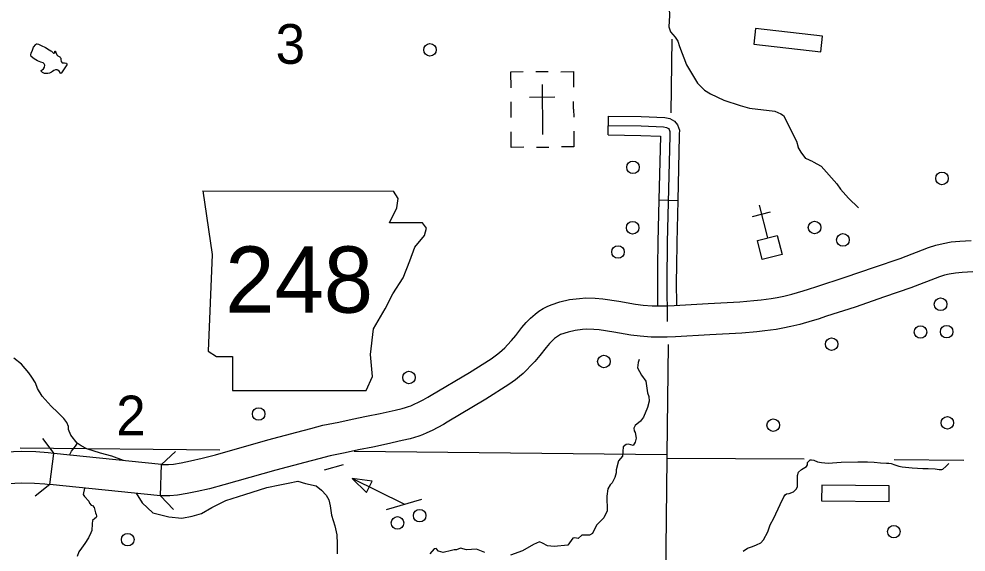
# Model space of a CAD drawing. Extents: x 1382482 to 1385815, y 1168351 to 1170484.
# Drawn here: x 1383865.9 to 1384167.8, y 1168828.2 to 1168998.2 of the extents above; entities that cross this region are included whole.
import ezdxf

# ---------------------------------------------------------------- set-up
doc = ezdxf.new("R2010")
doc.units = 0
for name, color, linetype in [('10', 7, 'Continuous'), ('21', 7, 'Continuous'), ('35', 7, 'Continuous'), ('37', 7, 'Continuous'), ('4', 7, 'Continuous'), ('45', 7, 'Continuous'), ('5', 7, 'Continuous'), ('57', 7, 'Continuous'), ('Default', 7, 'Continuous')]:
    doc.layers.add(name, color=color, linetype=linetype)

msp = doc.modelspace()

# ---------------------------------------------------------------- linework, layer by layer
at = {"layer": '10'}
for points in [[(1384035.51, 1168907.02), (1384038.28, 1168907.91), (1384041.38, 1168908.64), (1384044.58, 1168909.06), (1384046.58, 1168909.19), (1384049.61, 1168909.13), (1384052.01, 1168908.95), (1384057.11, 1168908.12), (1384062.4, 1168907.24), (1384064.88, 1168906.91), (1384067.79, 1168906.72), (1384072.42, 1168906.64), (1384074.72, 1168906.74), (1384085.56, 1168907.42), (1384095.67, 1168907.95), (1384100.13, 1168908.34), (1384102.5, 1168908.59), (1384105.71, 1168909.02), (1384107.58, 1168909.36), (1384109.77, 1168909.8), (1384112.26, 1168910.43), (1384115.91, 1168911.45), (1384117.59, 1168911.97), (1384120.25, 1168912.86), (1384129.31, 1168915.77), (1384138.6, 1168918.97), (1384146.83, 1168921.78), (1384155.88, 1168925.25), (1384158.16, 1168926.07), (1384160.51, 1168926.58), (1384163.12, 1168927.03), (1384165.85, 1168927.3), (1384169.46, 1168927.46)], [(1384169.94, 1168917.47), (1384166.56, 1168917.32), (1384164.47, 1168917.12), (1384162.43, 1168916.76), (1384160.9, 1168916.43), (1384159.35, 1168915.88), (1384150.24, 1168912.37), (1384141.84, 1168909.51), (1384132.47, 1168906.28), (1384123.37, 1168903.36), (1384120.64, 1168902.44), (1384118.71, 1168901.85), (1384114.85, 1168900.77), (1384111.99, 1168900.04), (1384109.46, 1168899.54), (1384107.28, 1168899.14), (1384103.7, 1168898.66), (1384101.08, 1168898.38), (1384096.36, 1168897.98), (1384086.13, 1168897.44), (1384075.24, 1168896.75), (1384072.55, 1168896.64), (1384067.38, 1168896.72), (1384063.88, 1168896.95), (1384060.91, 1168897.35), (1384055.49, 1168898.25), (1384050.83, 1168899.01), (1384049.13, 1168899.14), (1384046.81, 1168899.18), (1384045.56, 1168899.1), (1384043.19, 1168898.79), (1384040.94, 1168898.26), (1384038.56, 1168897.5)], [(1383911.35, 1168856.09), (1383911.55, 1168856.09), (1383913.5, 1168856.09), (1383915.15, 1168856.23), (1383917.61, 1168856.65), (1383920.61, 1168857.27), (1383924.24, 1168858.07), (1383928.53, 1168859.19), (1383945.17, 1168863.94), (1383954.43, 1168866.37), (1383958.89, 1168867.58), (1383962.79, 1168868.57), (1383967.85, 1168869.62), (1383972.1, 1168870.53), (1383976.69, 1168871.44), (1383980.99, 1168872.34), (1383985.83, 1168873.42), (1383988.06, 1168873.95), (1383989.08, 1168874.24), (1383990.03, 1168874.54), (1383990.78, 1168874.83), (1383991.83, 1168875.28), (1383993.25, 1168875.93), (1383994.73, 1168876.7), (1383996.21, 1168877.5), (1383997.25, 1168878.14), (1384009.53, 1168885.39), (1384016.42, 1168889.81), (1384018.11, 1168891.05), (1384019.12, 1168891.83), (1384019.94, 1168892.55), (1384020.75, 1168893.31), (1384021.67, 1168894.28), (1384022.85, 1168895.58), (1384024.24, 1168897.19), (1384026.22, 1168899.73), (1384027.59, 1168901.32), (1384028.94, 1168902.78), (1384030.4, 1168904.06), (1384031.64, 1168904.96), (1384033.02, 1168905.83), (1384034.22, 1168906.44), (1384035.51, 1168907.02)], [(1384038.56, 1168897.5), (1384037.25, 1168896.67), (1384036.64, 1168896.23), (1384035.93, 1168895.61), (1384035.04, 1168894.65), (1384033.95, 1168893.39), (1384031.97, 1168890.84), (1384030.34, 1168888.95), (1384029.01, 1168887.49), (1384027.81, 1168886.22), (1384026.64, 1168885.12), (1384025.48, 1168884.11), (1384024.15, 1168883.08), (1384022.09, 1168881.56), (1384014.77, 1168876.87), (1384002.41, 1168869.58), (1384001.21, 1168868.83), (1383999.41, 1168867.86), (1383997.65, 1168866.95), (1383995.89, 1168866.14), (1383994.52, 1168865.55), (1383993.33, 1168865.1), (1383991.99, 1168864.67), (1383990.59, 1168864.27), (1383988.07, 1168863.68), (1383983.1, 1168862.56), (1383978.68, 1168861.64), (1383974.12, 1168860.74), (1383969.92, 1168859.84), (1383965.04, 1168858.82), (1383961.43, 1168857.91), (1383957.01, 1168856.7), (1383947.8, 1168854.29), (1383931.17, 1168849.55), (1383926.57, 1168848.34), (1383922.7, 1168847.49), (1383919.48, 1168846.82), (1383916.42, 1168846.3), (1383913.92, 1168846.09), (1383911.39, 1168846.09), (1383911.03, 1168846.1), (1383911.35, 1168856.09)], [(1383875.74, 1168849.68), (1383877.01, 1168859.6), (1383875.13, 1168859.84), (1383871.26, 1168860.1), (1383866.76, 1168860.19), (1383864.1, 1168860.1), (1383860.56, 1168859.89), (1383855.45, 1168859.33), (1383849.15, 1168858.42), (1383842.26, 1168857.43), (1383831.66, 1168855.79), (1383823.49, 1168854.48), (1383815.39, 1168853.18)], [(1383911.35, 1168856.09), (1383877.01, 1168859.6)], [(1383815.39, 1168853.18), (1383816.97, 1168843.31), (1383825.07, 1168844.61), (1383833.22, 1168845.91), (1383843.73, 1168847.54), (1383850.57, 1168848.52), (1383856.71, 1168849.41), (1383861.41, 1168849.92), (1383864.57, 1168850.11), (1383866.83, 1168850.19), (1383870.83, 1168850.11), (1383874.16, 1168849.88), (1383875.74, 1168849.68)], [(1383911.03, 1168846.1), (1383875.74, 1168849.68)]]:
    msp.add_lwpolyline(points, dxfattribs=at)
at = {"layer": '21'}
for p, q in [((1383924.46, 1168943.3), (1383927.5, 1168923)), ((1383986.72, 1168940.93), (1383985.31, 1168943.27)), ((1383986.38, 1168937.89), (1383986.72, 1168940.93)), ((1383984.01, 1168933.15), (1383986.38, 1168937.89)), ((1383994.5, 1168933.15), (1383984.01, 1168933.15)), ((1383995.85, 1168931.46), (1383994.5, 1168933.15)), ((1383995.18, 1168929.09), (1383995.85, 1168931.46)), ((1383992.13, 1168925.37), (1383995.18, 1168929.09)), ((1383990.44, 1168920.97), (1383992.13, 1168925.37)), ((1383927.5, 1168923), (1383926.15, 1168892.21)), ((1383988.41, 1168915.56), (1383990.44, 1168920.97)), ((1383985.02, 1168910.48), (1383988.41, 1168915.56)), ((1383982.66, 1168905.74), (1383985.02, 1168910.48)), ((1383978.93, 1168899.31), (1383982.66, 1168905.74)), ((1383977.92, 1168891.19), (1383978.93, 1168899.31)), ((1383926.15, 1168892.21), (1383928.86, 1168890.52)), ((1383928.86, 1168890.52), (1383933.93, 1168890.52)), ((1383933.93, 1168890.52), (1383933.93, 1168879.69)), ((1383978.6, 1168884.09), (1383977.92, 1168891.19)), ((1383976.57, 1168879.69), (1383978.6, 1168884.09)), ((1383933.93, 1168879.69), (1383976.57, 1168879.69))]:
    msp.add_line(p, q, dxfattribs=at)
msp.add_lwpolyline([(1383924.46, 1168943.3), (1383985.31, 1168943.27)], dxfattribs=at)
at = {"layer": '35'}
for points in [[(1384073.22, 1169001.47), (1384073.28, 1168999.3), (1384073.03, 1168995.62), (1384073.6, 1168994.06), (1384075.1, 1168992.35), (1384075.95, 1168991.03), (1384076.48, 1168989.32), (1384078.72, 1168983.57), (1384082.25, 1168977.71), (1384084.46, 1168975.44), (1384086.31, 1168974.3), (1384090.56, 1168972.29), (1384095.85, 1168970.53), (1384098.78, 1168969.75), (1384106.9, 1168968.74), (1384108.82, 1168967.87), (1384109.58, 1168967.32), (1384113.77, 1168959.14), (1384114.34, 1168957.3)], [(1383874.03, 1168980.8), (1383873.37, 1168981.1), (1383873.13, 1168981.27), (1383872.92, 1168981.53), (1383872.92, 1168981.74), (1383873.25, 1168981.98), (1383873.7, 1168982.27), (1383874.01, 1168982.82), (1383874.09, 1168983.37), (1383873.92, 1168983.82), (1383873.56, 1168984.13), (1383872.84, 1168984.38), (1383871.8, 1168984.83), (1383870.67, 1168985.46), (1383869.75, 1168986.15), (1383869.61, 1168986.71), (1383869.71, 1168987.26), (1383870.14, 1168988.2), (1383870.53, 1168989.18), (1383871.23, 1168989.96), (1383871.49, 1168990.2), (1383871.68, 1168990.23), (1383872.1, 1168990.14), (1383872.9, 1168989.65), (1383874.35, 1168989), (1383875.54, 1168988.36), (1383876.05, 1168987.98), (1383876.24, 1168987.93)], [(1383876.24, 1168987.93), (1383876.73, 1168987.38), (1383876.93, 1168987.24), (1383877.11, 1168987.28), (1383877.26, 1168987.42), (1383877.28, 1168987.69), (1383877.28, 1168987.83), (1383877.32, 1168987.93), (1383877.48, 1168987.83), (1383877.65, 1168987.34), (1383878.01, 1168986.65), (1383878.24, 1168986.4), (1383878.85, 1168986.09), (1383879.04, 1168985.89), (1383879.24, 1168985.62), (1383879.26, 1168985.21), (1383879.38, 1168984.6), (1383879.65, 1168984.21), (1383879.87, 1168984.19), (1383880.43, 1168984.17), (1383880.8, 1168984.09), (1383881.02, 1168984.03), (1383881.1, 1168983.8), (1383881.12, 1168983.56), (1383879.45, 1168980.96), (1383879.24, 1168980.76), (1383879.02, 1168980.82), (1383878.98, 1168981.12), (1383878.73, 1168981.49), (1383878.3, 1168981.84), (1383878.01, 1168981.96), (1383877.5, 1168981.88), (1383876.99, 1168981.68), (1383876.6, 1168981.43), (1383876.21, 1168981.16), (1383875.66, 1168980.86), (1383875.05, 1168980.8), (1383874.27, 1168980.8), (1383874.03, 1168980.8)], [(1384119.12, 1168952.58), (1384116.77, 1168953.68), (1384115.27, 1168955.67), (1384114.34, 1168957.3)], [(1384119.12, 1168952.58), (1384121.64, 1168951.16), (1384126.66, 1168945.56), (1384127.83, 1168943.89), (1384130.32, 1168940.98), (1384133.49, 1168937.97)], [(1383899.24, 1168857.33), (1383895.5, 1168858.73), (1383891.83, 1168859.72), (1383887.56, 1168861.11), (1383885.75, 1168862.05), (1383884.41, 1168862.83), (1383882.43, 1168865.38), (1383881.69, 1168867.23), (1383881.65, 1168868.18), (1383881.09, 1168869.52), (1383880.23, 1168870.73), (1383878.29, 1168872.67), (1383876.17, 1168874.7), (1383873.32, 1168877.9), (1383871.77, 1168880.31), (1383871.17, 1168882.13), (1383870, 1168883.94), (1383869.01, 1168885.28), (1383866.68, 1168888.08), (1383864.27, 1168889.95)], [(1384063.6, 1168889.58), (1384063.28, 1168888.64), (1384063.09, 1168886.88), (1384064.35, 1168884.61), (1384065.72, 1168882.62), (1384066.23, 1168878.98), (1384066.72, 1168877.78), (1384066.81, 1168876.3), (1384066.31, 1168874.21), (1384064.94, 1168871.19), (1384063.99, 1168869.91), (1384062.32, 1168868.53), (1384061.93, 1168867.65), (1384061.98, 1168866.81), (1384062.3, 1168866.25), (1384062.6, 1168864.45), (1384062.37, 1168863.2), (1384061.69, 1168862.16), (1384060.17, 1168862.55), (1384059.49, 1168862.5), (1384058.54, 1168861.69), (1384058.25, 1168858.73), (1384056.98, 1168857.27), (1384056.28, 1168854.38), (1384056.29, 1168853.42), (1384055.82, 1168851.94), (1384054.96, 1168850.25), (1384054.33, 1168849.6), (1384053.66, 1168848.27), (1384053.28, 1168846.03), (1384053.39, 1168841.26), (1384052.29, 1168839.09), (1384049.96, 1168836.71), (1384048.7, 1168834.1), (1384047.82, 1168833.57), (1384045.35, 1168833.51), (1384044.12, 1168832.5), (1384043.12, 1168832.73), (1384042.48, 1168832.6), (1384040.82, 1168830.39), (1384036.54, 1168829.95), (1384034.39, 1168830.1), (1384032.82, 1168831.04), (1384031.86, 1168831.4), (1384029.87, 1168830.54), (1384026.45, 1168828.51)], [(1383881.95, 1168859.09), (1383882.6, 1168860.33), (1383883.85, 1168861.97), (1383884.33, 1168862.57), (1383884.41, 1168862.83)], [(1384096.74, 1168828.39), (1384098.14, 1168829.38), (1384099.69, 1168829.98), (1384101.06, 1168830.46), (1384102.39, 1168831.08), (1384103.28, 1168832.01), (1384104.64, 1168834.63), (1384105.38, 1168836.88), (1384106.56, 1168838.92), (1384108.56, 1168843.31), (1384109.74, 1168845.79), (1384110.18, 1168846.42), (1384110.55, 1168846.68), (1384111.48, 1168846.79), (1384112.8, 1168847.38), (1384113.62, 1168848.19), (1384114.13, 1168848.97), (1384114.1, 1168850.22), (1384114.06, 1168851.55), (1384114.06, 1168852.55), (1384114.39, 1168853.66), (1384115.32, 1168854.47), (1384116.93, 1168855.46), (1384117.23, 1168856.02), (1384117.26, 1168856.68), (1384117.71, 1168857.16), (1384118.08, 1168857.53), (1384118.56, 1168857.53), (1384119.26, 1168857.42), (1384120.51, 1168856.94), (1384121.7, 1168856.76), (1384123.87, 1168856.54), (1384127.97, 1168856.83), (1384133.33, 1168856.9), (1384136.4, 1168856.94), (1384138.54, 1168856.79), (1384140.5, 1168856.61), (1384142.42, 1168856.54), (1384143.19, 1168856.46), (1384143.97, 1168856.35), (1384145.11, 1168856.02), (1384146.4, 1168855.57), (1384147.46, 1168855.32), (1384150.68, 1168854.98), (1384154.04, 1168854.76), (1384155.74, 1168854.76), (1384157.99, 1168854.69), (1384159.28, 1168854.43), (1384160.13, 1168854.47), (1384160.43, 1168854.58), (1384161.39, 1168855.43), (1384162.28, 1168856.35)], [(1383927.31, 1168842.35), (1383931.83, 1168844.61), (1383937.91, 1168846.48), (1383944.89, 1168848.71), (1383949.09, 1168849.63), (1383951.66, 1168850.15), (1383954.79, 1168850.76), (1383957.25, 1168850.05), (1383960.61, 1168849.25), (1383962.3, 1168847.9), (1383963.86, 1168846.34), (1383964.7, 1168844.83), (1383965.11, 1168842.87), (1383965.48, 1168839.92), (1383966.58, 1168836.57), (1383967.24, 1168833.66), (1383967.32, 1168830.76), (1383967.32, 1168827.61)], [(1383886.8, 1168848.56), (1383886.39, 1168846.49), (1383886.8, 1168845.84), (1383888.11, 1168844.4), (1383888.31, 1168843.71), (1383888.85, 1168843.14), (1383889.34, 1168842.97), (1383889.83, 1168842.4), (1383890.11, 1168841.5), (1383890.28, 1168840.64), (1383890.44, 1168840.11), (1383890.56, 1168839.74), (1383890.64, 1168839.45), (1383890.52, 1168839.21), (1383890.03, 1168838.88), (1383889.3, 1168838.23), (1383889.17, 1168837.12), (1383889.09, 1168835.04), (1383888.76, 1168834.26), (1383888.07, 1168832.66), (1383886.92, 1168830.9), (1383885.82, 1168829.43), (1383885, 1168828.24), (1383884.39, 1168826.72)], [(1383903.25, 1168846.89), (1383905.19, 1168843.82), (1383908.51, 1168840.68), (1383913.64, 1168839.4), (1383917.77, 1168839), (1383921.11, 1168839.62), (1383924.07, 1168840.48), (1383927.31, 1168842.35)], [(1384014.38, 1168828.05), (1384011.74, 1168829.07), (1384008.58, 1168828.89), (1384006.66, 1168829.39), (1384005.39, 1168828.9), (1384004.57, 1168828.88), (1384003.74, 1168828.66), (1384001.1, 1168827.97), (1383999.68, 1168828.46), (1383998.84, 1168829.27), (1383998.29, 1168829.21), (1383996.89, 1168827.55)], [(1384026.45, 1168828.51), (1384022.58, 1168827.16)]]:
    msp.add_lwpolyline(points, dxfattribs=at)
at = {"layer": '37'}
for points in [[(1383873.34, 1168864.35), (1383877.01, 1168859.6)], [(1383911.35, 1168856.09), (1383915.73, 1168860.2)], [(1383875.74, 1168849.68), (1383871, 1168846.01)], [(1383915.13, 1168841.72), (1383911.03, 1168846.1)]]:
    msp.add_lwpolyline(points, dxfattribs=at)
at = {"layer": '4'}
for points in [[(1384074.02, 1168991.68), (1384073.74, 1168968.22)], [(1384072.84, 1168894.38), (1384072.4, 1168859.16), (1384072.39, 1168858.03), (1384070.68, 1168705.11)]]:
    msp.add_lwpolyline(points, dxfattribs=at)
at = {"layer": '45'}
for p, q in [((1384053.76, 1168961.16), (1384053.83, 1168967.16)), ((1384069.89, 1168940.44), (1384075.89, 1168940.29))]:
    msp.add_line(p, q, dxfattribs=at)
for points in [[(1384053.83, 1168967.16), (1384064.27, 1168967.03), (1384071.75, 1168966.76), (1384073.41, 1168966.38), (1384074.84, 1168965.57), (1384075.85, 1168964.41), (1384076.45, 1168962.73), (1384076.4, 1168961.38)], [(1384053.8, 1168964.16), (1384064.2, 1168964.03), (1384071.36, 1168963.77), (1384072.31, 1168963.56), (1384072.91, 1168963.21), (1384073.22, 1168962.87), (1384073.43, 1168962.26), (1384073.39, 1168961.01), (1384072.57, 1168926.89), (1384072.44, 1168914.46), (1384072.49, 1168901.64)], [(1384053.76, 1168961.16), (1384064.12, 1168961.03), (1384070.38, 1168960.81)], [(1384070.38, 1168960.81), (1384069.89, 1168940.44)], [(1384076.4, 1168961.38), (1384076.39, 1168960.92), (1384075.89, 1168940.29)], [(1384069.89, 1168940.44), (1384069.57, 1168926.94), (1384069.49, 1168919.28)], [(1384075.89, 1168940.29), (1384075.57, 1168926.84), (1384075.49, 1168919.22)], [(1384069.49, 1168919.28), (1384069.44, 1168914.47), (1384069.47, 1168906.69)], [(1384075.49, 1168919.22), (1384075.44, 1168914.45), (1384075.47, 1168906.79)]]:
    msp.add_lwpolyline(points, dxfattribs=at)
at = {"layer": '5'}
for points in [[(1383929.92, 1168860.66), (1383866.3, 1168861.33)], [(1384072.4, 1168859.16), (1383972.76, 1168860.21)], [(1384116.2, 1168857.74), (1384072.39, 1168858.03)], [(1384167.11, 1168857.4), (1384144.89, 1168857.55)]]:
    msp.add_lwpolyline(points, dxfattribs=at)
at = {"layer": '57'}
for p, q in [((1384100.74, 1168995.08), (1384100.18, 1168990.11)), ((1384122.1, 1168992.64), (1384100.74, 1168995.08)), ((1384121.54, 1168987.67), (1384122.1, 1168992.64)), ((1384100.18, 1168990.11), (1384121.54, 1168987.67)), ((1384034.64, 1168981.31), (1384030.64, 1168981.28)), ((1384032.65, 1168977.29), (1384032.78, 1168961.29)), ((1384022.7, 1168971.68), (1384022.74, 1168966.68)), ((1384028.69, 1168973.26), (1384036.72, 1168973.33)), ((1384042.72, 1168969.38), (1384042.7, 1168971.84)), ((1384032.72, 1168969.29), (1384032.72, 1168969.29)), ((1384032.72, 1168969.29), (1384032.72, 1168969.29)), ((1384042.72, 1168969.38), (1384042.74, 1168966.84)), ((1384030.84, 1168957.28), (1384034.84, 1168957.31)), ((1384101.87, 1168938.79), (1384104.5, 1168928.34)), ((1384099.69, 1168935.15), (1384105.51, 1168936.61)), ((1384121.82, 1168849.47), (1384121.78, 1168844.47)), ((1384143.31, 1168849.31), (1384121.82, 1168849.47)), ((1384143.28, 1168844.31), (1384143.31, 1168849.31)), ((1384121.78, 1168844.47), (1384143.28, 1168844.31))]:
    msp.add_line(p, q, dxfattribs=at)
for points in [[(1384026.62, 1168981.25), (1384022.62, 1168981.21), (1384022.66, 1168976.21)], [(1384038.62, 1168981.34), (1384042.62, 1168981.38), (1384042.66, 1168976.38)], [(1384026.82, 1168957.25), (1384022.82, 1168957.21), (1384022.78, 1168962.21)], [(1384042.78, 1168962.38), (1384042.82, 1168957.38), (1384038.82, 1168957.34)]]:
    msp.add_lwpolyline(points, dxfattribs=at)
msp.add_lwpolyline([(1384102.87, 1168921.5), (1384101.35, 1168927.55), (1384107.62, 1168929.13), (1384109.15, 1168923.08)], close=True, dxfattribs=at)
at = {"layer": 'Default'}
for points in [[(1383963.28, 1168854.34), (1383969.33, 1168856.1)], [(1383988.68, 1168843.38), (1383972.11, 1168851.66)], [(1383983.08, 1168841.75), (1383994.29, 1168845.01)]]:
    msp.add_lwpolyline(points, dxfattribs=at)
msp.add_lwpolyline([(1383976.67, 1168847.1), (1383978.49, 1168850.75), (1383972.11, 1168851.66)], close=True, dxfattribs=at)
for centre in [(1383996.91, 1168988.32), (1384061.62, 1168950.85), (1384160.15, 1168947.31), (1384061.53, 1168931.57), (1384119.53, 1168931.66), (1384128.57, 1168927.69), (1384056.86, 1168923.84), (1384159.7, 1168907.18), (1384153.3, 1168898.32), (1384161.65, 1168898.43), (1384124.97, 1168894.46), (1384052.37, 1168888.93), (1383990.22, 1168883.83), (1383942.29, 1168872.2), (1384161.86, 1168869.37), (1384106.35, 1168868.61), (1383993.61, 1168839.78), (1383986.57, 1168837.45), (1384144.78, 1168834.67), (1383900.56, 1168832.12)]:
    msp.add_circle(centre, 2, dxfattribs=at)

# ---------------------------------------------------------------- texts
at = {"layer": '21'}
msp.add_text('248', height=21.12, dxfattribs=at).set_placement((1383931.64, 1168904.49))
at = {"layer": '37'}
msp.add_text('2', height=12.67, dxfattribs=at).set_placement((1383896.87, 1168865.37))
at = {"layer": '57'}
msp.add_text('3', height=12.67, dxfattribs=at).set_placement((1383947.69, 1168983.85))

doc.saveas('drawing.dxf')
